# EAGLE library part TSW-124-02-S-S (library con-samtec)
THROUGH-HOLE .025" SQ POST HEADER Source: Samtec TSW.pdf
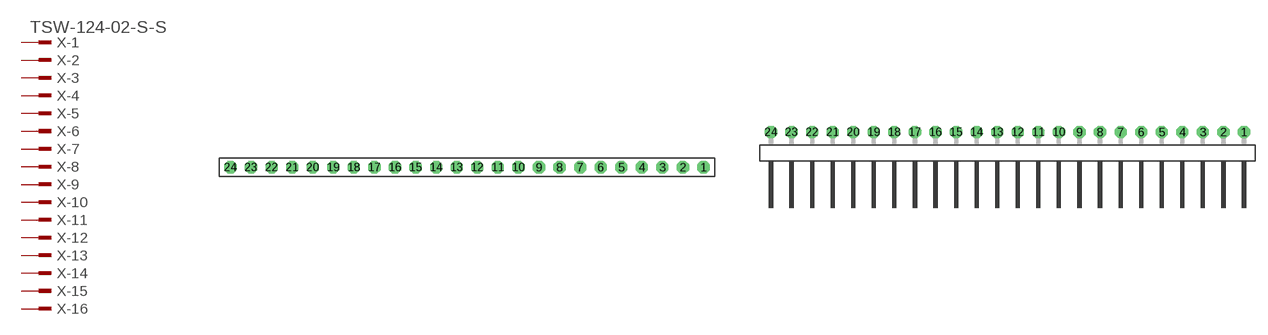
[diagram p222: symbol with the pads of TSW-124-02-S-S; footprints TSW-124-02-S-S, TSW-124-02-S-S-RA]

Designator prefix X; gates -1=MPINV -2=MPIN -3=MPIN -4=MPIN -5=MPIN -6=MPIN -7=MPIN -8=MPIN -9=MPIN -10=MPIN -11=MPIN -12=MPIN -13=MPIN -14=MPIN -15=MPIN -16=MPIN -17=MPIN -18=MPIN -19=MPIN -20=MPIN -21=MPIN -22=MPIN -23=MPIN -24=MPIN

## TSW-124-02-S-S (OC_FARNELL: unknown; OC_NEWARK: unknown)  [TSW-124-02-S-S]
1  -1:1  pas
2  -2:1  pas
3  -3:1  pas
4  -4:1  pas
5  -5:1  pas
6  -6:1  pas
7  -7:1  pas
8  -8:1  pas
9  -9:1  pas
10  -10:1  pas
11  -11:1  pas
12  -12:1  pas
13  -13:1  pas
14  -14:1  pas
15  -15:1  pas
16  -16:1  pas
17  -17:1  pas
18  -18:1  pas
19  -19:1  pas
20  -20:1  pas
21  -21:1  pas
22  -22:1  pas
23  -23:1  pas
24  -24:1  pas

## TSW-124-02-S-S-RA (OC_FARNELL: unknown; OC_NEWARK: unknown)  [TSW-124-02-S-S-RA]
Pads as for TSW-124-02-S-S

## Footprint TSW-124-02-S-S (pad centres in mm)
THROUGH-HOLE .025" SQ POST HEADER Source: Samtec TSW.pdf
drill 1 pad 1.5 octagon: 1 29.21,0; 2 26.67,0; 3 24.13,0; 4 21.59,0; 5 19.05,0; 6 16.51,0; 7 13.97,0; 8 11.43,0; 9 8.89,0; 10 6.35,0; 11 3.81,0; 12 1.27,0; 13 -1.27,0; 14 -3.81,0; 15 -6.35,0; 16 -8.89,0; 17 -11.43,0; 18 -13.97,0; 19 -16.51,0; 20 -19.05,0; 21 -21.59,0; 22 -24.13,0; 23 -26.67,0; 24 -29.21,0

## Footprint TSW-124-02-S-S-RA (pad centres in mm)
THROUGH-HOLE .025" SQ POST HEADER Source: Samtec TSW.pdf
drill 1 pad 1.5 octagon: 1 29.21,1.524; 2 26.67,1.524; 3 24.13,1.524; 4 21.59,1.524; 5 19.05,1.524; 6 16.51,1.524; 7 13.97,1.524; 8 11.43,1.524; 9 8.89,1.524; 10 6.35,1.524; 11 3.81,1.524; 12 1.27,1.524; 13 -1.27,1.524; 14 -3.81,1.524; 15 -6.35,1.524; 16 -8.89,1.524; 17 -11.43,1.524; 18 -13.97,1.524; 19 -16.51,1.524; 20 -19.05,1.524; 21 -21.59,1.524; 22 -24.13,1.524; 23 -26.67,1.524; 24 -29.21,1.524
